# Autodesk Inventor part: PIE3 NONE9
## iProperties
Shininess: 64.0
Length Units: 11269
Angle Units: 11279
Time Units: 11290
Mass Units: 11286
Length Display Precision: 3
Angle Display Precision: 2
Compacted: True
Part Number: PIE3 NONE9
Document SubType Name: Modeling
Created: 2004-08
Designer: John Blackburn
Manufacturer: Standard
Standards Organization: Custom
Density: 0.0
Volumn: 0.0
Area: 0.0
PropertySet Name: Model Information
Control State: 0
Master: False
Checked Out: False
Author: John Blackburn
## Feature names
1. Erst1
